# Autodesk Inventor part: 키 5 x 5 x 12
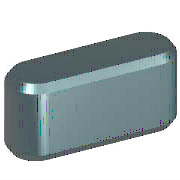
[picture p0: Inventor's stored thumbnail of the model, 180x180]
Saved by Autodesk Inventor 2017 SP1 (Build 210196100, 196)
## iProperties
IsCustomPart: 1
Created: 2012-02
Part Number: 키 5 x 5 x 12
Material: 강철, 연강
Description: 키 및 해당 키홈
Document SubType Name: Modeling
Standard: KS B 1311
Designer: mduedu
Standards Organization: KS
Language: ko-KR
Size Designation: 5 x 5 x 12
Categories: <MemberInstance><Categories><Category DisplayName="샤프트 부품" InternalName="7f7aeb1f-a693-4053-b835-cee3144e0d98" Mnemonic="SHFT"><Category DisplayName="키" Interna
Density: 7.86 g/cm^3
Mass: 2.11085 g
Surface Area: 2.43471 cm^2
Volume: 0.268556 cm^3
Appearance: 노란색
Author: mduedu
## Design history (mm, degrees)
workplane "Work Plane1"
workplane "Work Plane2"
sketch "스케치1"
  geometry: L1 (2.5, 2.5)-(9.5, 2.5); L2 (9.5, -2.5)-(2.5, -2.5); L3 (0, 9.4)-(0, -7.4) reference; L4 (-5, 0)-(30, 0) reference; L5 (12, 0)-(12, 7); A1 r 2.5 centre (2.5, 0) between (2.5, 2.5) and (2.5, -2.5); A2 r 2.5 centre (9.5, 0) between (9.5, -2.5) and (9.5, 2.5)
  constraints: 6 end point, 5 point on circle, 4 tangent, 3 point on line, 2 centre point, 1 horizontal, 1 parallel, 1 perpendicular
  dimensions: "d0" = 2.5 radius of A1 (= 0.5 x PB); "d13" = 2.5 radius of A2 (= 0.5 x PB); "d14" = 12 distance between parallel lines of L5 L3 (= NLG)
extrude "본체1" new body sketch "스케치1" taper "d3" = 0 deg; stored distance "d4" = 10
workplane "Work Plane3"
body "Solid1"
chamfer "모따기1" distance "d8" = 0.4 (= PHH); stored, may be unused: second distance "d9" = 0.4 (= PHH), angle "d15" = 45 deg
other parameters: "d1" = -3 (= -PNT), "d2" = 2 (= PH - PNT), "NLG" = 12 [user parameter; used in 3 equation terms], "PB" = 5 [user parameter; used in 2 equation terms], "PNT" = 3 [user parameter; used in 2 equation terms], "PH" = 5 [user parameter; used in 1 equation term], "PHH" = 0.4 [user parameter; used in 2 equation terms], "d10" = 0, "d16" = 0, "d17" = 0, "d18" = 0, "WDMIN" = 12 [user parameter], "PLB2" = 12 (= NLG) [user parameter], "WDMAX" = 17 [user parameter], "PLB1" = 12 (= NLG) [user parameter], "RR" = 0.16 [user parameter], "PUEB" = 2.3 [user parameter]
